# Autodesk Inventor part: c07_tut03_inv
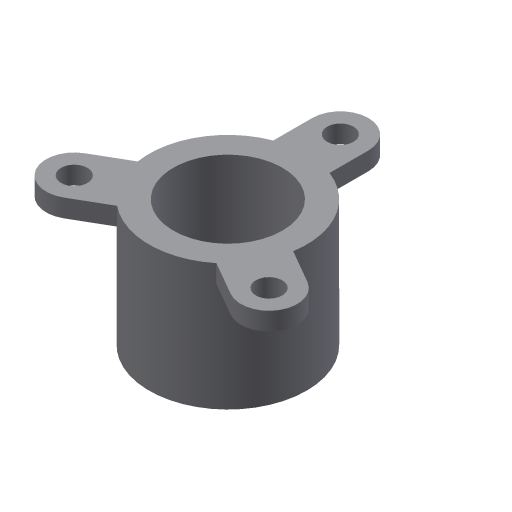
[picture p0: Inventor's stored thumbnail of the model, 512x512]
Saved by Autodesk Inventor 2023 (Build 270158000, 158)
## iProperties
Created: 2010-03
Part Number: c07_tut03_inv
Document SubType Name: Modeling
Designer: CADSoft
Density: 1 g/cm^3
Material: Generic
Appearance: Default
Author: CADSoft
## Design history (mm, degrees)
sketch "Sketch1"
  geometry: C1 r 97 at (0, 0); C2 r 140 at (0, 0); 1 further point
  constraints: 2 centre point, 2 coincident
  dimensions: "d0" = 194 diameter of C1; "d1" = 280 diameter of C2
extrude "Extrusion1" new body sketch "Sketch1" stored distance "d2" = 225; taper "d3" = 0 deg
pattern_circular "Circular Pattern2" dims angle "d38" = 360 deg
body "Solid1"
sketch "Sketch5"
  geometry: L1 (-50, 200)-(-50, 130.767); L2 (50, 200)-(50, 130.767); L3 (0, 0)-(0, 306.095); C1 r 97 at (0, 0) reference; C2 r 23.5 at (0, 200); A1 r 140 centre (0, 0) between (-50, 130.767) and (50, 130.767) reference; A2 r 50 centre (0, 200) between (50, 200) and (-50, 200); A3 r 140 centre (0, 0) between (50, 130.767) and (-50, 130.767)
  constraints: 7 point on circle, 6 end point, 3 centre point, 2 coincident, 2 tangent, 1 other
  dimensions: "d32" = 200 distance of A2.centre C1.centre; "d33" = 50 radius of A2; "d34" = 47 diameter of C2
extrude "Extrusion2" join sketch "Sketch5" distance "d35" = 32; taper "d36" = 0 deg
